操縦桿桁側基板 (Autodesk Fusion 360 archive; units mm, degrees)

design "回路図 操縦桿　改　20260626"
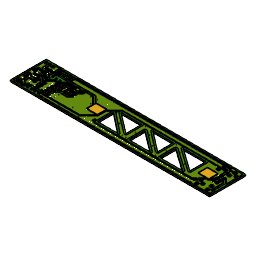
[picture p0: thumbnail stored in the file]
sketch "スケッチ" plane through (0, 0, 0) normal (0, 0, 1) x axis (1, 0, 0)
  line L1 (142, -1.2) -> (0, -1.2)
  line L2 (142, 24.5) -> (142, -1.2)
  line L3 (0, 24.5) -> (142, 24.5)
  line L4 (0, -1.2) -> (0, 24.5)
  line L5 (94.2015, 4.2331) -> (79.1927, 4.2331)
  line L6 (79.1927, 15.5993) -> (94.2015, 4.2331)
  line L7 (79.1927, 4.2331) -> (79.1927, 15.5993)
  line L8 (120, 6.7385) -> (103.8413, 18.1658)
  line L9 (120, 18.1658) -> (120, 6.7385)
  line L10 (103.8413, 18.1658) -> (120, 18.1658)
  line L11 (71.1392, 4.2331) -> (56.7405, 4.2331)
  line L12 (56.7405, 15.5993) -> (71.1392, 4.2331)
  line L13 (56.7405, 4.2331) -> (56.7405, 15.5993)
  line L14 (117.2638, 4.2331) -> (101.1568, 4.2331)
  line L15 (101.1568, 15.5382) -> (117.2638, 4.2331)
  line L16 (101.1568, 4.2331) -> (101.1568, 15.5382)
  line L17 (74.1898, 7.0441) -> (59.5471, 18.1658)
  line L18 (74.1898, 18.1658) -> (74.1898, 7.0441)
  line L19 (59.5471, 18.1658) -> (74.1898, 18.1658)
  line L20 (96.764, 7.0441) -> (82.2433, 18.1658)
  line L21 (96.764, 18.1658) -> (96.764, 7.0441)
  line L22 (82.2433, 18.1658) -> (96.764, 18.1658)
canvas "キャンバス1"
canvas "キャンバス2"
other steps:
base_feature "基準フィーチャ1"
base_feature "基準フィーチャ1"
base_feature "基準フィーチャ1"
base_feature "基準フィーチャ1"
box_primitive "直方体プリミティブ1" DistanceX 87.35 DistanceY 21.2 DistanceZ 0.1 OffsetDistanceX 0 OffsetDistanceY 0
base_feature "基準フィーチャ1"
box_primitive "直方体プリミティブ1" DistanceX 9.502 DistanceY 1.88 DistanceZ 1.578 OffsetDistanceX 0 OffsetDistanceY 0
base_feature "基準フィーチャ1"
base_feature "基準フィーチャ1"
base_feature "基準フィーチャ1"
base_feature "基準フィーチャ1"
base_feature "基準フィーチャ1"
box_primitive "直方体プリミティブ1" DistanceX 18.865 DistanceY 23.015 DistanceZ 0.1 OffsetDistanceX 0 OffsetDistanceY 0
base_feature "基準フィーチャ1"
pcbextrude "PCB 押し出し1"
pcbextrude "PCB 押し出し1"
pcbextrude "PCB 押し出し1"
pcbextrude "PCB 押し出し1"
extrude "押し出し" sketch "スケッチ" blind 1.037
pcbextrude "PCB 押し出し1"
pcbextrude "PCB 押し出し2"
create_component "CreateComponent1"
create_component "CreateComponent2"
create_component "CreateComponent3"
create_component "CreateComponent4"
create_component "CreateComponent5"
create_component "CreateComponent6"
create_component "CreateComponent1"
create_component "CreateComponent2"
create_component "CreateComponent3"
create_component "CreateComponent4"
create_component "CreateComponent6"
create_component "CreateComponent7"
create_component "CreateComponent8"
create_component "CreateComponent1"
create_component "CreateComponent9"
create_component "CreateComponent1"
create_component "CreateComponent10"
create_component "CreateComponent11"
as_built_joint "現況"
create_component "CreateComponent13"
create_component "CreateComponent1"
